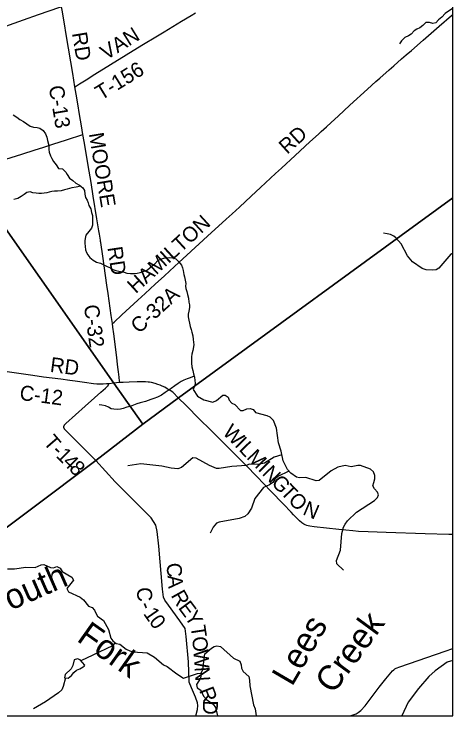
# Model space of a CAD drawing. Extents: x 0 to 34, y 0 to 22.
# Drawn here: x 29.916 to 31.588, y 14.306 to 16.977 of the extents above; entities that cross this region are included whole.
import ezdxf

# ---------------------------------------------------------------- set-up
doc = ezdxf.new("R2010")
doc.units = 0
for name, color, linetype in [('GM_X_Corporation', 7, 'Continuous'), ('GM_X_County_Road', 7, 'Continuous'), ('GM_X_County_Road_Text', 7, 'Continuous'), ('GM_X_Minor_Lake', 7, 'Continuous'), ('GM_X_Minor_River', 7, 'Continuous'), ('GM_X_Minor_River_Text', 7, 'Continuous'), ('GM_X_State_Route', 7, 'Continuous'), ('GM_X_Township_Road', 7, 'Continuous'), ('GM_X_Township_Road_Text', 7, 'Continuous')]:
    doc.layers.add(name, color=color, linetype=linetype)

msp = doc.modelspace()

# ---------------------------------------------------------------- linework, layer by layer
at = {"layer": 'GM_X_Corporation'}
for points in [[(31.5875, 16.2767), (31.5875, 21.1059), (24.7875, 21.1059), (24.7875, 14.3059), (28.9316, 14.3059), (29.0116, 14.3654), (30.2271, 15.2782), (30.4064, 15.4161), (30.5426, 15.5161)], [(31.5875, 16.2767), (31.5875, 21.1059), (25.6086, 21.1059), (25.0178, 20.9472), (26.0175, 20.4289), (26.9873, 19.9283), (27.122, 19.8586), (27.3085, 19.7612), (27.7955, 19.0474), (28.3618, 18.3058), (29.4482, 16.7745), (29.7308, 16.376), (30.2965, 15.5727), (30.4064, 15.4161), (30.5426, 15.5161)], [(24.7875, 21.0754), (24.7875, 14.3059), (28.9316, 14.3059), (29.0116, 14.3654), (30.2271, 15.2782), (30.4064, 15.4161), (30.2965, 15.5727), (29.7308, 16.376), (29.4482, 16.7745), (28.3618, 18.3058), (27.7955, 19.0474), (27.3085, 19.7612), (27.122, 19.8586), (26.9873, 19.9283), (26.0175, 20.4289), (25.0178, 20.9472)], [(28.9316, 14.3059), (31.5875, 14.3059), (31.5875, 16.2767), (30.5426, 15.5161), (30.4064, 15.4161), (30.2271, 15.2782), (29.0116, 14.3654)], [(28.9316, 14.3059), (31.5875, 14.3059), (31.5875, 16.2767), (30.5426, 15.5161), (30.4064, 15.4161), (30.2271, 15.2782), (29.0116, 14.3654)]]:
    msp.add_lwpolyline(points, close=True, dxfattribs=at)
at = {"layer": 'GM_X_County_Road'}
msp.add_line((30.2967, 15.5722), (30.2768, 15.5701), dxfattribs=at)
for points in [[(30.1483, 16.7001), (30.1399, 16.7503), (30.116, 16.8918), (30.1072, 16.9464), (30.0996, 16.9918), (30.0975, 17.0042)], [(30.2908, 15.7987), (30.2974, 15.8048), (30.3271, 15.8322), (30.3875, 15.8876), (30.4159, 15.9137), (30.454, 15.9484), (30.4887, 15.9804), (30.5271, 16.0157), (30.544, 16.0313), (30.5738, 16.0586), (30.6534, 16.1317), (30.7237, 16.1957), (30.7471, 16.217), (30.7745, 16.2423), (30.8195, 16.2842), (30.8542, 16.3163), (30.8739, 16.3343), (30.9122, 16.3697), (30.9346, 16.3904), (30.9862, 16.438), (31.0429, 16.4901), (31.0752, 16.5192), (31.0862, 16.5292), (31.1058, 16.5474), (31.1241, 16.5642), (31.15, 16.5884), (31.1951, 16.6302), (31.2617, 16.6909), (31.2941, 16.7199), (31.3091, 16.733), (31.3448, 16.7648), (31.3622, 16.7798), (31.3917, 16.8056), (31.4094, 16.8211), (31.429, 16.8384), (31.4739, 16.8777), (31.5345, 16.93), (31.5823, 16.9707), (31.5875, 16.9752)], [(30.1785, 16.5179), (30.1731, 16.5511), (30.1661, 16.5947), (30.1592, 16.6351), (30.1531, 16.6713), (30.1483, 16.7001)], [(29.7311, 16.3754), (29.7358, 16.3768), (29.7619, 16.385), (29.775, 16.3891), (29.8241, 16.4047), (29.885, 16.4243), (29.9454, 16.4436), (29.9963, 16.4598), (30.0265, 16.4693), (30.0644, 16.4813), (30.1162, 16.4979), (30.1785, 16.5179)], [(30.2908, 15.7987), (30.2863, 15.8295), (30.274, 15.9131), (30.2692, 15.9456), (30.2538, 16.0557), (30.2464, 16.1079), (30.2459, 16.1117), (30.2455, 16.114), (30.2451, 16.1165), (30.2415, 16.1387), (30.2392, 16.1515), (30.2364, 16.1667), (30.2311, 16.198), (30.2177, 16.2839), (30.2093, 16.3354), (30.2019, 16.3789), (30.183, 16.4922), (30.1785, 16.5179)], [(30.3189, 15.5743), (30.3183, 15.5796), (30.3165, 15.5954), (30.314, 15.6151), (30.3116, 15.633), (30.3062, 15.6799), (30.2963, 15.76), (30.2928, 15.7852), (30.2908, 15.7987)], [(30.2768, 15.5701), (30.2677, 15.5692), (30.2552, 15.5682), (30.2515, 15.568), (30.2452, 15.5679), (30.2412, 15.5679), (30.2347, 15.5682), (30.2312, 15.5684), (30.2189, 15.5696), (30.1845, 15.5743), (30.1494, 15.5793), (30.1291, 15.582), (30.0946, 15.5868), (30.028, 15.5954), (29.9881, 15.601), (29.9351, 15.6084), (29.8717, 15.6172), (29.867, 15.6177)], [(30.3189, 15.5743), (30.3159, 15.5741), (30.2967, 15.5722)], [(30.5428, 15.5156), (30.5205, 15.5379), (30.5105, 15.5442), (30.4998, 15.5511), (30.4899, 15.5567), (30.4804, 15.5613), (30.4728, 15.5643), (30.4641, 15.5676), (30.4537, 15.5712), (30.4402, 15.5743), (30.4318, 15.5759), (30.4268, 15.5765), (30.4166, 15.5777), (30.3848, 15.5767), (30.355, 15.5757), (30.3313, 15.575), (30.3248, 15.5747), (30.3189, 15.5743)], [(31.5875, 14.9958), (31.5715, 14.9963), (31.4822, 14.9993), (31.3337, 15.0033), (31.264, 15.0063), (31.2275, 15.0081), (31.2063, 15.01), (31.1795, 15.0125), (31.153, 15.0153), (31.0592, 15.0258), (31.0421, 15.0278), (31.0365, 15.0289), (31.0309, 15.0306), (31.0252, 15.033), (31.02, 15.0356), (31.0123, 15.0405), (31.0027, 15.0485), (30.9806, 15.0709), (30.9714, 15.0809), (30.9422, 15.1113), (30.8946, 15.1607), (30.8404, 15.2171), (30.8001, 15.2586), (30.7513, 15.3075), (30.7172, 15.3415), (30.6628, 15.3964), (30.6242, 15.4343), (30.57, 15.4885), (30.5428, 15.5156)], [(30.608, 14.3059), (30.6153, 14.3303), (30.6164, 14.3458), (30.6149, 14.3563), (30.6067, 14.3779), (30.5917, 14.4128), (30.5826, 14.4342), (30.5805, 14.5117), (30.5717, 14.6076), (30.5676, 14.6392), (30.5478, 14.6682), (30.5039, 14.7271), (30.4907, 14.746), (30.485, 14.7583), (30.4812, 14.7884), (30.4674, 14.9523), (30.4616, 15.0075), (30.4566, 15.0319), (30.4387, 15.0601), (30.3008, 15.1966), (30.2273, 15.2777)]]:
    msp.add_lwpolyline(points, dxfattribs=at)
at = {"layer": 'GM_X_Minor_Lake'}
for points in [[(30.1676, 14.5188), (30.1578, 14.5231), (30.1449, 14.5199), (30.14, 14.498), (30.1333, 14.4855), (30.1114, 14.4635), (30.1089, 14.4507), (30.1222, 14.4497), (30.1356, 14.4593), (30.1433, 14.471), (30.1545, 14.4799), (30.1671, 14.4846)], [(30.1671, 14.4846), (30.1798, 14.4924), (30.1832, 14.4953), (30.1856, 14.4988), (30.1676, 14.5188)]]:
    msp.add_lwpolyline(points, dxfattribs=at)
at = {"layer": 'GM_X_Minor_River'}
for points in [[(31.5875, 16.9984), (31.5807, 16.9935), (31.57, 16.9871), (31.5582, 16.9792), (31.5456, 16.9653), (31.5329, 16.9544), (31.5222, 16.9434), (31.5104, 16.9412), (31.4975, 16.9444), (31.4846, 16.9445), (31.4728, 16.9335), (31.4609, 16.9241), (31.4495, 16.9193), (31.4392, 16.9133), (31.4277, 16.9001), (31.4182, 16.8937), (31.4048, 16.8874), (31.3918, 16.8753)], [(31.3918, 16.8753), (31.3841, 16.8628)], [(29.9135, 16.5937), (29.9274, 16.5845), (29.9387, 16.5756), (29.9519, 16.5672), (29.9651, 16.5591), (29.9772, 16.5506), (29.9908, 16.5456), (30.0037, 16.5443), (30.0143, 16.5423), (30.0275, 16.5331), (30.0365, 16.5209), (30.0406, 16.5087), (30.0435, 16.4957), (30.0479, 16.4813), (30.0489, 16.4714), (30.0489, 16.4615), (30.0495, 16.4509), (30.0551, 16.4376), (30.0607, 16.4276), (30.0667, 16.4154), (30.0764, 16.4028), (30.0854, 16.3891), (30.1002, 16.3871), (30.1133, 16.3752), (30.1189, 16.3656), (30.1279, 16.3526), (30.1396, 16.3427), (30.152, 16.3331), (30.1652, 16.3254), (30.1788, 16.315), (30.184, 16.3055), (30.1862, 16.2914), (30.1887, 16.2785), (30.1951, 16.2678), (30.1984, 16.2583), (30.201, 16.248), (30.2081, 16.2358), (30.2106, 16.2221), (30.2147, 16.2095), (30.2153, 16.197), (30.2152, 16.1871), (30.2155, 16.1731), (30.2116, 16.1614), (30.2012, 16.1493), (30.1901, 16.135), (30.1865, 16.1232), (30.1857, 16.1138), (30.1864, 16.1043), (30.187, 16.0917), (30.1884, 16.0792), (30.1925, 16.0693), (30.1974, 16.0598), (30.2045, 16.0502), (30.2169, 16.0395), (30.2297, 16.0325), (30.2453, 16.0286), (30.2607, 16.0205), (30.2713, 16.0158), (30.283, 16.0104), (30.2928, 16.0046), (30.3042, 16.0007), (30.3156, 15.9987), (30.3353, 15.9948), (30.3458, 15.9909), (30.3602, 15.99), (30.3743, 15.9898), (30.3845, 15.9901)], [(30.17, 16.3217), (30.1527, 16.3179), (30.1367, 16.3154), (30.1181, 16.3106), (30.1078, 16.3077), (30.0956, 16.3044), (30.0823, 16.3026), (30.0702, 16.3027), (30.0607, 16.302), (30.0504, 16.2995), (30.0405, 16.2969), (30.0306, 16.2947), (30.0211, 16.2936), (30.0109, 16.2941), (30.0003, 16.295), (29.9878, 16.2966), (29.978, 16.3001), (29.9654, 16.298), (29.9543, 16.2901), (29.9429, 16.2826), (29.9303, 16.2747), (29.9151, 16.2715)], [(31.3697, 16.1247), (31.3618, 16.1309), (31.3493, 16.1375), (31.3372, 16.1407), (31.3235, 16.1427)], [(31.5875, 16.0672), (31.5791, 16.0627), (31.5341, 16.0098), (31.5237, 16.0039), (31.5096, 16.0018), (31.4853, 16.0037), (31.4706, 16.0089), (31.4337, 16.0338), (31.4139, 16.0572), (31.3902, 16.1028), (31.3697, 16.1247)], [(30.3845, 15.9901), (30.3971, 15.9927), (30.4081, 15.9964), (30.4207, 16.0012), (30.4318, 16.0091), (30.4425, 16.0188), (30.452, 16.0267), (30.4643, 16.0384), (30.4757, 16.0443), (30.4867, 16.0473), (30.4974, 16.0487), (30.5092, 16.0497), (30.5202, 16.0492), (30.5319, 16.0453), (30.5435, 16.0342), (30.5544, 16.0208), (30.5574, 16.0106), (30.5607, 16.0003), (30.5625, 15.9862), (30.565, 15.9763), (30.5683, 15.9642), (30.5705, 15.9512), (30.5696, 15.9418), (30.5707, 15.9323), (30.5744, 15.9205), (30.5766, 15.9098), (30.5802, 15.8961), (30.5824, 15.8805), (30.5845, 15.8699), (30.5844, 15.86), (30.5824, 15.846), (30.5797, 15.835), (30.5792, 15.8244), (30.5817, 15.8122), (30.5839, 15.8008), (30.5865, 15.7883), (30.5905, 15.7761), (30.5931, 15.7662), (30.5964, 15.7525), (30.5985, 15.7388), (30.5999, 15.7278), (30.601, 15.7179), (30.597, 15.6963), (30.5938, 15.6827), (30.5922, 15.6728), (30.5914, 15.6603), (30.5916, 15.6478), (30.5938, 15.6337), (30.5974, 15.6208), (30.6, 15.6079), (30.6033, 15.5949), (30.6051, 15.5828), (30.6065, 15.5718), (30.6063, 15.5677)], [(30.6022, 15.5993), (30.5866, 15.5928), (30.5755, 15.5884), (30.5633, 15.5835), (30.5531, 15.5791), (30.5416, 15.5708), (30.529, 15.5622), (30.5145, 15.5521), (30.5027, 15.5442), (30.492, 15.5364), (30.4771, 15.5266), (30.4622, 15.5184), (30.4485, 15.5136), (30.4371, 15.5095), (30.4169, 15.5025), (30.4062, 15.4996), (30.3967, 15.4974), (30.3834, 15.4933), (30.3705, 15.4885), (30.3587, 15.4837), (30.3454, 15.4811), (30.3317, 15.4763), (30.321, 15.4734), (30.3096, 15.4723), (30.2963, 15.4728), (30.2861, 15.4748), (30.2759, 15.4802), (30.2642, 15.4857), (30.2502, 15.4888), (30.2407, 15.4897)], [(30.6063, 15.5677), (30.5983, 15.5474), (30.6154, 15.5225), (30.6387, 15.5088), (30.6734, 15.5003), (30.6872, 15.5066), (30.711, 15.5259), (30.7205, 15.5261), (30.7321, 15.5191), (30.7349, 15.507), (30.745, 15.4954), (30.7574, 15.4911), (30.7779, 15.468), (30.7889, 15.4678), (30.8023, 15.4744), (30.8148, 15.4761), (30.8265, 15.4718), (30.8366, 15.4595)], [(31.1704, 14.861), (31.1456, 14.8846), (31.1443, 14.898), (31.1589, 14.9361), (31.1637, 14.9999), (31.171, 15.0241), (31.1776, 15.0357), (31.1854, 15.0489), (31.2202, 15.0818), (31.289, 15.1256), (31.2998, 15.1372), (31.3038, 15.1478), (31.3005, 15.1577), (31.2885, 15.1697), (31.2819, 15.182), (31.2862, 15.1948), (31.2906, 15.2084), (31.2901, 15.2213), (31.2846, 15.2347), (31.2729, 15.2452), (31.2351, 15.2587), (31.2256, 15.2592), (31.2004, 15.2535), (31.1765, 15.2592), (31.1491, 15.2531), (31.1241, 15.2387), (31.0779, 15.2018), (31.0664, 15.2008), (31.0278, 15.2136), (31.0035, 15.2121), (30.9921, 15.2149), (30.9699, 15.2301), (30.9572, 15.2436), (30.9406, 15.2765), (30.9335, 15.3135), (30.923, 15.3448), (30.9155, 15.4004), (30.9042, 15.4306), (30.8911, 15.4433), (30.8805, 15.4476), (30.8366, 15.4595)], [(30.8449, 15.2628), (30.8115, 15.2638), (30.8015, 15.2583), (30.7461, 15.2553), (30.6971, 15.2474), (30.6865, 15.2479), (30.6609, 15.2593), (30.6097, 15.287), (30.5969, 15.2876), (30.5538, 15.2511), (30.5401, 15.2464), (30.5151, 15.2483), (30.4796, 15.2561), (30.399, 15.2646), (30.3496, 15.2581)], [(30.9362, 15.2996), (30.9062, 15.2903), (30.87, 15.2677), (30.8449, 15.2628)], [(30.9631, 15.2373), (30.921, 15.2168), (30.9094, 15.2074), (30.902, 15.1946), (30.8889, 15.185), (30.8655, 15.1747), (30.8325, 15.133)], [(30.8325, 15.133), (30.8202, 15.0968), (30.8058, 15.075), (30.7954, 15.0649), (30.7737, 15.0573), (30.6973, 15.0437), (30.687, 15.0389), (30.6742, 15.0247), (30.6636, 15.0014)], [(29.891, 14.8659), (29.9175, 14.8659), (29.9609, 14.872), (29.9965, 14.8711), (30.019, 14.8814), (30.0293, 14.8824), (30.0545, 14.8713), (30.067, 14.8696), (30.0796, 14.8747), (30.0924, 14.8681), (30.0997, 14.8551), (30.1362, 14.8337), (30.1421, 14.8222), (30.1173, 14.7911), (30.1236, 14.7781), (30.1676, 14.7573), (30.1807, 14.7472), (30.2001, 14.7242), (30.2136, 14.7187), (30.2226, 14.7083), (30.2277, 14.6965), (30.234, 14.6861), (30.2572, 14.6687), (30.2764, 14.6346), (30.285, 14.6019), (30.2924, 14.5915), (30.3055, 14.5822), (30.3191, 14.579), (30.3434, 14.5596), (30.3566, 14.5537), (30.3683, 14.5501), (30.4232, 14.5459), (30.4506, 14.5291), (30.4854, 14.5001), (30.4998, 14.4946), (30.5365, 14.4663), (30.5616, 14.45), (30.615, 14.4678), (30.6283, 14.4691), (30.6353, 14.483), (30.6431, 14.5428), (30.6681, 14.5644), (30.6777, 14.57), (30.6883, 14.5728), (30.7023, 14.5696), (30.752, 14.5263), (30.7765, 14.5146), (30.7812, 14.5005), (30.7818, 14.4875), (30.7888, 14.4745), (30.8108, 14.4556), (30.8129, 14.4427), (30.8137, 14.4199), (30.8283, 14.3481)], [(30.3011, 14.5854), (30.2906, 14.5733), (30.2157, 14.5377), (30.1703, 14.5157)], [(31.5875, 14.5169), (31.5658, 14.5104), (31.5196, 14.4776), (31.4957, 14.456), (31.4562, 14.4106), (31.4166, 14.3588), (31.3922, 14.3059)], [(30.1116, 14.4505), (30.1038, 14.4177), (30.0976, 14.4053), (30.0852, 14.3934), (30.0358, 14.3593), (29.9899, 14.3327)], [(30.6283, 14.4691), (30.6257, 14.4502), (30.6105, 14.425), (30.6137, 14.4124), (30.6272, 14.4035), (30.6379, 14.3806), (30.6491, 14.3683), (30.6738, 14.3512), (30.6835, 14.3381), (30.6904, 14.3059)], [(30.8283, 14.3481), (30.8341, 14.3324), (30.8377, 14.3059)]]:
    msp.add_lwpolyline(points, dxfattribs=at)
at = {"layer": 'GM_X_State_Route'}
msp.add_lwpolyline([(31.1938, 14.3059), (31.204, 14.3089), (31.2187, 14.3145), (31.2268, 14.3187), (31.2373, 14.3268), (31.2532, 14.3444), (31.3064, 14.416), (31.3317, 14.4474), (31.3576, 14.478), (31.362, 14.4812), (31.3665, 14.4847), (31.3716, 14.4874), (31.3846, 14.4932), (31.5582, 14.5522), (31.5875, 14.5626)], dxfattribs=at)
at = {"layer": 'GM_X_Township_Road'}
for points in [[(29.4484, 16.774), (29.4549, 16.7763), (29.5083, 16.795), (29.5394, 16.8058), (29.5838, 16.8218), (29.6229, 16.8361), (29.6783, 16.8564), (29.7309, 16.8753), (29.8083, 16.9025), (29.8995, 16.9352), (29.9522, 16.9541), (30.0094, 16.9746), (30.0904, 17.0031), (30.092, 17.0034), (30.0942, 17.0037), (30.0975, 17.0042)], [(30.1483, 16.7001), (30.1538, 16.7034), (30.166, 16.7109), (30.1907, 16.7265), (30.2243, 16.7477), (30.3427, 16.821), (30.4025, 16.8577), (30.4622, 16.8936), (30.4882, 16.9093), (30.5541, 16.9493), (30.5904, 16.9708), (30.6075, 16.981)], [(30.2273, 15.2777), (30.1858, 15.3199), (30.122, 15.3832), (30.1121, 15.3933), (30.1106, 15.3949), (30.1094, 15.3963), (30.1087, 15.3973), (30.108, 15.3984), (30.1075, 15.3991), (30.1069, 15.4002), (30.1066, 15.401), (30.1063, 15.4017), (30.1061, 15.4026), (30.106, 15.4036), (30.1059, 15.4047), (30.1059, 15.4056), (30.1062, 15.4079), (30.1064, 15.4088), (30.1068, 15.4098), (30.1072, 15.4107), (30.1078, 15.4117), (30.1081, 15.4123), (30.1089, 15.4135), (30.1097, 15.4146), (30.1109, 15.4159), (30.1119, 15.4169), (30.1132, 15.4181), (30.1865, 15.484), (30.2221, 15.5159), (30.247, 15.5381), (30.2642, 15.5535), (30.2727, 15.561), (30.2733, 15.5616), (30.274, 15.5624), (30.2745, 15.563), (30.2752, 15.5639), (30.2757, 15.5648), (30.2759, 15.5655), (30.2763, 15.5665), (30.2765, 15.5674), (30.2767, 15.5687), (30.2768, 15.5695), (30.2768, 15.5701)]]:
    msp.add_lwpolyline(points, dxfattribs=at)

# ---------------------------------------------------------------- texts
at = {"layer": 'GM_X_County_Road_Text'}
for s, height, rotation, p in [('RD', 0.05682, 279.463, (30.1367, 16.9036)), ('C-13', 0.05682, 279.6319, (30.048, 16.7004)), ('RD', 0.05682, 42.2075, (30.9562, 16.4407)), ('MOORE', 0.05682, 279.5245, (30.2008, 16.5212)), ('HAMILTON', 0.05682, 42.4629, (30.3794, 15.9106)), ('RD', 0.05682, 278.4101, (30.2717, 16.0883)), ('C-32A', 0.05682, 42.526, (30.3921, 15.758)), ('C-32', 0.05682, 278.037, (30.1818, 15.8672)), ('RD', 0.05682, 352.5688, (30.0512, 15.6154)), ('C-12', 0.05682, 352.4006, (29.935, 15.509)), ('W', 0.0568, 314.0208, (30.7074, 15.382)), ('I', 0.0568, 314.0235, (30.7531, 15.3347)), ('L', 0.0568, 314.0196, (30.7694, 15.3179)), ('M', 0.0568, 314.02, (30.7989, 15.2873)), ('I', 0.0568, 314.0202, (30.8417, 15.243)), ('N', 0.0568, 314.0221, (30.858, 15.2262)), ('G', 0.0568, 314.0211, (30.8927, 15.1903)), ('T', 0.0568, 314.0196, (30.9274, 15.1543)), ('O', 0.0568, 314.1335, (30.9571, 15.1237)), ('N', 0.0568, 336.911, (31.0121, 15.0739)), ('C', 0.0568, 274.8103, (30.4963, 14.8862)), ('A', 0.0568, 274.8589, (30.5003, 14.8397)), ('C', 0.0568, 274.8748, (30.3829, 14.7933)), ('R', 0.0568, 299.0416, (30.5121, 14.765)), ('E', 0.0568, 306.6328, (30.5392, 14.7173)), ('-', 0.0568, 292.1278, (30.3912, 14.7287)), ('1', 0.0568, 304.7839, (30.4065, 14.6951)), ('0', 0.0568, 307.2559, (30.428, 14.6642)), ('Y', 0.0568, 301.4876, (30.5638, 14.6843)), ('T', 0.0568, 278.521, (30.5879, 14.6473)), ('O', 0.0568, 275.608, (30.5941, 14.606)), ('W', 0.0568, 274.0233, (30.5989, 14.5567)), ('N', 0.0568, 273.6597, (30.6035, 14.4911)), ('R', 0.0568, 291.2705, (30.62, 14.4034)), ('D', 0.0568, 269.3279, (30.6359, 14.3656))]:
    msp.add_text(s, height=height, rotation=rotation, dxfattribs=at).set_placement(p)
at = {"layer": 'GM_X_Minor_River_Text'}
for s, height, rotation, p in [('South', 0.09469, 23.7431, (29.8255, 14.6719)), ('Creek', 0.0947, 53.7431, (31.1316, 14.3857)), ('Fork', 0.09469, 324.6704, (30.1509, 14.5936)), ('Lees', 0.0947, 59.743, (30.9747, 14.415))]:
    msp.add_text(s, height=height, rotation=rotation, dxfattribs=at).set_placement(p)
at = {"layer": 'GM_X_Township_Road_Text'}
for s, height, rotation, p in [('VAN', 0.05682, 31.6691, (30.267, 16.7999)), ('T-156', 0.05682, 31.5888, (30.2479, 16.6468)), ('T', 0.0568, 310.6715, (30.0253, 15.3455)), ('-', 0.0568, 315.3316, (30.0564, 15.3096)), ('1', 0.0568, 315.1398, (30.073, 15.2932)), ('4', 0.0568, 315.2122, (30.0978, 15.2684)), ('8', 0.0568, 315.2245, (30.1227, 15.2438))]:
    msp.add_text(s, height=height, rotation=rotation, dxfattribs=at).set_placement(p)

doc.saveas('drawing.dxf')
